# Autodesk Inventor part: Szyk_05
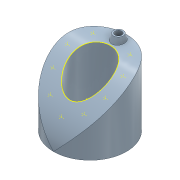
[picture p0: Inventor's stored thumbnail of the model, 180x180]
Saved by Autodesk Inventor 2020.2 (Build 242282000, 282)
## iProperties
Created: 2016-07
Part Number: Szyk_05
Material: Ogólne
Document SubType Name: Modeling
Designer: F.Stasiak
Density: 1 g/cm^3
Appearance: Stalowoniebieska
Manager: www.cadconsulting.pl
Company: Fabian Stasiak CAD Consulting
Author: F.Stasiak
Subject: Zbiór ćwiczeń. Autodesk Inventor 2020. Kurs podstawowy
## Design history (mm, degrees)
sketch "Szkic1"
  geometry: L1 (0, -45)-(0, -25); L2 (0, 25)-(0, 45); C1 r 35 at (0, 0); A1 r 25 centre (0, 0) between (0, -25) and (0, 25); A2 r 45 centre (0, 0) between (0, -45) and (0, 45); 1 further point
  constraints: 4 end point, 4 point on circle, 3 centre point, 3 coincident, 3 point on line, 1 vertical
  dimensions: "d0" = 50 diameter of A1; "d1" = 90 diameter of A2; "d33" = 70 diameter of C1
extrude "Wyciągnięcie proste1" new body sketch "Szkic1" distance "d2" = 80; taper "d3" = 0 deg
sketch "Szkic2"
  geometry: L1 (45, 80)-(-45, 80) reference; L2 (-45, 0)-(45, 0) reference; L3 (65.332, 80)-(24.668, 80); L4 (-45, 16.608)-(-45, -16.608); A1 r 50.149 centre (5.149, 0) between (-43.327, 12.843) and (-43.327, -12.843); 5 further points
  constraints: 4 end point, 4 midpoint, 2 horizontal, 2 vertical, 1 centre point, 1 point on circle, 7 other
feature "PowWyciągnięciaProstego1" sketch "Szkic2" dims "d4" = 108.75, "d5" = 0
feature "Podział2"
sketch "Szkic 3D4"
  node "Przecięcie 3D3"
node "Punkt konstrukcyjny2"
node "Płaszczyzna konstrukcyjna5"
pattern_linear "Szyk prostokątny1"
sketch "Szkic 3D6"
sketch "Szkic 3D7"
sketch "Szkic9"
  geometry: C1 r 6 at (0, 35); 2 further points
  constraints: 1 centre point, 1 coincident, 1 vertical alignment
  dimensions: "d43" = 12 diameter of C1
extrude "Wyciągnięcie proste4" join sketch "Szkic9" distance "d44" = 10; taper "d45" = 15 deg
sketch "Szkic10"
  geometry: C1 r 6 at (0, 0) reference; C2 r 4.25 at (0, 0); 1 further point
  constraints: 1 centre point, 1 coincident
  dimensions: "d48" = 8.5 diameter of C2
extrude "Wyciągnięcie proste5" cut sketch "Szkic10" distance "d49" = 12; taper "d50" = 0 deg
node "Bryła1"
body "Srf1"
node "Punkt konstrukcyjny3"
node "Punkt konstrukcyjny4"
node "Punkt konstrukcyjny5"
node "Punkt konstrukcyjny6"
node "Punkt konstrukcyjny7"
node "Punkt konstrukcyjny8"
node "Punkt konstrukcyjny9"
node "Punkt konstrukcyjny10"
node "Punkt konstrukcyjny11"
other parameters: "d42" = 86.5
